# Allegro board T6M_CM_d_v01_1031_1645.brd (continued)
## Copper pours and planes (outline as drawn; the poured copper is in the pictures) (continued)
PV_VDDR_NODE1_V1 on TOP (solid shape): 46.98,11.32 47.03,11.31 47.07,11.28 47.6,10.76 48.55,10.76 48.86,10.76 48.95,10.72 48.98,10.63 48.98,10.24 48.97,10.22 48.98,10.21 48.98,9.97 48.95,9.88 48.86,9.84 47.62,9.84 47.35,9.58 46.78,9.58 46.66,9.7 46.66,11.29 46.69,11.32
PV_VDDR_NODE1_VREF on TOP (solid shape): 49.07,8.41 49.07,7.82 48.66,7.41 47.65,7.41 47.32,7.08 46.64,7.08 46.42,7.29 46.42,8.43 46.48,8.49 49,8.49
PV_VDDR_NODE1_VREF_R on TOP (solid shape): 25.34,11.39 25.34,6.41 25.03,6.11 23.95,6.11 23.69,6.36 23.69,9.65 22.81,10.54 22.21,10.54 22.16,10.59 22.16,11.29 22.34,11.47 25.26,11.47
PV_VTT_DDR_NODE1 on TOP (solid shape): outline of 267 points within 115.18,16.72 127.52,30.28
PV_VTT_DDR_NODE1 on BOTTOM (solid shape): 127.21,27.16 127.3,27.12 127.34,27.03 127.34,26.28 127.43,26.19 127.43,25.93 127.84,25.53 127.84,24.77 127.71,24.65 127.09,24.65 126.95,24.8 126.93,24.9 126.93,24.97 126.59,25.31 125.82,26.08 125.82,27.03 125.86,27.12 125.95,27.16
PV_VTT_DDR_NODE1_REFIN on TOP (solid shape): 130.01,26.2 130.01,25.68 130.22,25.47 130.22,23.66 129.97,23.41 128.36,23.41 128.31,23.46 128.31,24.74 128.38,24.81 128.91,24.81 128.99,24.89 128.99,25.28 129.04,25.34 129.04,26.35 129.06,26.37 129.85,26.37
PV_VTT_DDR_NODE1_REFOUT on TOP (solid shape): 126.55,21.17 126.55,20.06 125.95,19.46 125.95,18.99 125.76,18.8 125.02,18.8 124.95,18.87 124.95,21.03 125.12,21.2 126.53,21.2
PWRGD_NODE1_P1V05_SUS_PG on TOP (solid shape): 106.49,136.85 106.49,135.8 106.47,135.78 103.66,135.78 103.22,136.22 103.22,137.39 103.27,137.44 105.9,137.44
SATA_P7 on TOP (solid shape): 165.56,55.07 165.74,55 165.81,54.81 165.91,54.33 166.21,53.94 166.25,53.89 166.26,53.84 166.26,51.33 166.11,51.18 163.39,51.18 162.82,51.75 157.87,51.75 157.83,51.75 157.79,51.78 157.73,51.84 156.71,51.84 156.54,51.84 156.42,51.96 156.39,52 156.38,52.05 156.38,54.87 156.59,55.07
SATA_P7 on BOTTOM (solid shape): 165.56,55.07 165.74,55 165.81,54.81 165.91,54.33 166.21,53.94 166.25,53.89 166.26,53.84 166.26,51.33 166.11,51.18 163.39,51.18 162.82,51.75 157.87,51.75 157.83,51.75 157.79,51.78 157.73,51.84 156.71,51.84 156.54,51.84 156.42,51.96 156.39,52 156.38,52.05 156.38,54.87 156.59,55.07
SATA_VCONT_NODE1 on TOP (solid shape): 149.33,69.39 149.33,66.78 149.13,66.58 147.73,66.58 147.59,66.72 147.59,69.2 147.88,69.49 149.23,69.49
SATA_VCONT_NODE1 on TOP (solid shape): 162.41,70.06 162.41,69.78 162.19,69.56 162.19,69.34 162.04,69.19 162.04,67.92 161.99,67.88 161.08,67.88 161.04,67.93 161.04,68.08 161.05,68.14 161.36,68.44 161.46,68.8 161.46,69.57 161.46,69.64 161.49,69.7 161.98,70.19 162.28,70.19
SIO_AVCC on TOP (solid shape): 153.93,28.73 154.43,28.23 156.59,28.23 156.85,27.97 156.85,26.96 156.66,26.77 156.53,26.77 156.16,26.4 156.16,26.01 156.12,25.97 155.36,25.97 155.06,26.27 153.97,26.27 153.66,25.96 153.05,25.96 152.95,26.06 152.95,28.39 153.67,29.11 153.67,30.97 153.93,30.97
SIO_VCCH on TOP (solid shape): 138.55,34.42 138.55,33.5 138.28,33.23 137.65,33.23 137.36,32.95 137.36,31.67 137.32,31.58 137.24,31.54 136.43,31.54 135.89,31.01 135.8,30.97 135.71,31.01 135.22,31.5 135.22,31.86 135.48,32.12 135.51,32.12 135.51,32.16 135.58,32.23 135.58,34.58 135.6,34.61 138.37,34.61
SIO_VCCH on BOTTOM (solid shape): 138.19,34.49 138.19,33.72 137.99,33.51 137.52,33.51 137.36,33.36 137.36,31.11 137.03,30.78 135.94,30.78 135.02,31.7 135.02,34.43 135.19,34.61 138.08,34.61
SW_P1V05_NODE1_BT on TOP (solid shape): 31.63,129.42 31.63,128.66 31.56,128.59 30.93,128.59 30.13,129.38 29.21,129.38 29.2,129.4 29.2,129.65 29.2,129.65 31.4,129.65
SW_P1V05_NODE1_DRVH on TOP (solid shape): 28.47,129.15 28.47,128.14 28.59,128.02 28.59,127.23 28.59,126.89 28.56,126.86 28.56,126.18 28.55,126.17 28.02,126.17 28,126.19 28,126.57 28.21,126.79 28.21,129.14 28.25,129.17 28.45,129.17
SW_P1V05_NODE1_DRVL on TOP (solid shape): 34.21,126.84 34.21,126.29 34.07,126.15 32.32,126.15 32.26,126.2 32.26,126.98 34.07,126.98
SW_P1V05_NODE1_DRVL on TOP (solid shape): 27.97,129.15 27.97,127.71 27.93,127.67 27.93,126.9 27.84,126.81 27.58,126.81 27.49,126.9 27.49,127.78 27.72,128.01 27.72,129.14 27.75,129.17 27.96,129.17
SW_P1V05_NODE1_DRVL on BOTTOM (solid shape): 31.36,127.08 32.84,127.08 32.87,127.05 33.09,126.98 33.31,127.05 33.35,127.08 34.2,127.08 34.28,127 34.28,126.34 34.24,126.25 34.15,126.21 30.77,126.21 29.01,127.97 27.99,127.97 27.94,127.92 27.94,126.89 27.79,126.74 27.25,126.74 27.17,126.81 26.91,127.06 26.91,128.68 26.95,128.77 27.04,128.81 29.63,128.81
SW_P1V05_NODE1_PH on TOP (solid shape): 30.73,128.22 31.61,128.22 31.97,127.87 31.97,123.65 32.18,123.45 33.37,123.45 33.48,123.34 33.48,120.59 33.36,120.47 30.13,120.47 29.97,120.63 29.97,126.9 29.85,127.02 29,127.02 28.94,127.08 28.94,128.12 28.71,128.35 28.71,129.07 28.75,129.11 29.84,129.11
SW_P1V05_NODE1_VIN_FLT on TOP (solid shape): 29.62,126.62 29.62,123.94 29.58,123.89 28.8,123.89 28.23,123.33 28.23,119.29 27.95,119.01 25.47,119.01 25.28,119.2 25.28,125.75 25.43,125.9 28.78,125.9 28.82,125.94 28.82,126.6 28.86,126.63 29.61,126.63
SW_P1V05_NODE1_VIN_FLT on BOTTOM (solid shape): 28.23,125.7 28.23,121.15 28.03,120.95 25.54,120.95 25.28,121.21 25.28,125.75 25.45,125.92 28.01,125.92
SW_P1V8_STB_NODE1_BT on TOP (solid shape): 113.24,154.11 113.24,153.19 112.81,152.76 110.99,152.76 110.92,152.84 110.92,153.89 111.17,154.14 113.21,154.14
SW_P1V8_STB_NODE1_PH on TOP (solid shape): 112.67,157.86 112.67,156.2 113.27,155.6 113.27,154.43 113.24,154.4 110.73,154.4 110.62,154.29 110.62,153.62 110.48,153.48 108.05,153.48 107.63,153.9 107.63,157.76 107.8,157.93 112.6,157.93
SW_P3V3_NODE1_BT on TOP (solid shape): 85.58,8.39 85.58,7.33 85.33,7.08 83.29,7.08 83.27,7.11 83.27,8.03 83.69,8.46 85.51,8.46
SW_P3V3_NODE1_PH on TOP (solid shape): 88.32,6.69 88.32,3.32 88.29,3.29 83.9,3.29 83.83,3.36 83.83,5.03 83.24,5.62 83.24,6.08 83.24,6.08 83.24,6.57 83.25,6.58 83.24,6.59 83.24,6.79 83.27,6.82 88.19,6.82
SW_P3V3_STB_NODE1_BT on TOP (solid shape): 61.34,111.92 61.34,110.86 61.1,110.61 59.05,110.61 59.03,110.64 59.03,111.57 59.46,111.99 61.27,111.99
SW_P3V3_STB_NODE1_PH on TOP (solid shape): 64.08,110.22 64.08,106.85 64.05,106.82 60.71,106.82 60.48,107.05 59.75,107.05 59.59,107.2 59.59,108.56 59,109.15 59,110.32 59.03,110.35 63.95,110.35
SW_P5V_STB_NODE1_BT on TOP (solid shape): 89.72,154.08 89.72,153.15 89.29,152.73 87.48,152.73 87.4,152.8 87.4,153.86 87.65,154.1 89.69,154.1
SW_P5V_STB_NODE1_PH on TOP (solid shape): 89.16,157.68 89.16,156.16 89.75,155.57 89.75,154.4 89.72,154.37 84.79,154.37 84.66,154.5 84.66,157.68 84.78,157.8 89.04,157.8
SW_PV_VDDR_NODE1_BT on TOP (solid shape): 52.14,9.56 52.52,9.56 53.14,8.94 53.97,8.94 54,8.91 54,8.09 53.84,7.93 53,7.93 51.51,9.42 51.24,9.42 51.23,9.44 51.23,9.54 51.25,9.57 52.14,9.57
SW_PV_VDDR_NODE1_DRVH on TOP (solid shape): 55.21,6.74 55.06,6.58 53.84,6.58 53.78,6.64 53.78,7.31 53.91,7.44 54.42,7.44 54.76,7.78 55.21,7.78
SW_PV_VDDR_NODE1_DRVH on TOP (solid shape): 53.54,11.04 53.54,10.79 52.99,10.24 52.16,10.24 52.15,10.23 51.25,10.23 51.24,10.24 51.24,10.36 51.25,10.37 52.51,10.37 53.28,11.14 53.44,11.14
SW_PV_VDDR_NODE1_DRVH on BOTTOM (solid shape): 55.19,9.72 55.19,6.69 55.02,6.52 53.85,6.52 53.79,6.58 53.79,9.14 52.63,10.29 52.63,10.57 53.23,11.17 53.75,11.17
SW_PV_VDDR_NODE1_DRVL on TOP (solid shape): 55.22,12 55.22,11.55 55.18,11.5 53.27,11.5 52.4,10.64 51.25,10.64 51.24,10.65 51.24,10.76 51.26,10.78 52.09,10.78 53.33,12.02 55.21,12.02
SW_PV_VDDR_NODE1_PH on TOP (solid shape): 60.63,12.42 60.63,9.33 60.55,9.24 53.28,9.24 52.71,9.81 52.6,9.81 52.59,9.82 51.25,9.82 51.23,9.84 51.23,9.96 51.25,9.98 53.12,9.98 53.2,9.98 54.46,11.24 57.7,11.24 57.93,11.47 57.93,12.62 57.99,12.68 60.38,12.68
SW_PV_VDDR_NODE1_VIN_FLT on TOP (solid shape): 57.5,8.83 57.5,8.05 58.07,7.48 63.67,7.48 63.95,7.2 63.95,5.26 63.75,5.05 61.19,5.05 60.53,4.4 53.11,4.4 52.97,4.54 52.97,5.63 53.06,5.73 55.11,5.73 55.47,6.08 55.47,7.99 55.4,8.06 54.78,8.06 54.76,8.08 54.76,8.86 54.77,8.88 57.45,8.88
SW_PV_VDDR_NODE1_VIN_FLT on BOTTOM (solid shape): 64.17,7.11 64.17,4.76 63.89,4.48 55.55,4.48 55.31,4.72 55.31,5.77 55.32,5.78 55.32,5.97 55.81,6.46 55.81,7.01 56.22,7.43 63.85,7.43
SW_VR_PVCCP_NODE1_VIN_FLT on TOP (solid shape): 131.09,127.44 131.09,124.35 130.93,124.18 130.2,124.18 127.65,124.18 126.98,124.18 126.91,124.11 123.41,124.11 123.22,123.92 123.22,123.22 123.18,123.13 123.09,123.09 122.53,123.09 122.46,123.16 122.46,127.22 122.62,127.37 123.18,127.37 123.27,127.46 131.07,127.46
SW_VR_PVCCP_NODE1_VIN_FLT on BOTTOM (solid shape): 131.11,127.31 131.11,124.29 131,124.18 130.2,124.18 127.65,124.18 126.88,124.18 126.8,124.11 123.41,124.11 123.22,123.92 123.22,123.22 123.18,123.13 123.09,123.09 122.53,123.09 122.46,123.16 122.46,127.22 122.62,127.37 123.18,127.37 123.27,127.46 130.96,127.46
USB_OC_PU on TOP (solid shape): 179.2,96.17 179.2,95.91 179.19,95.89 179.17,95.78 179.19,95.67 179.2,95.65 179.2,94.86 178.34,94 177.87,94 177.78,94.09 177.78,94.38 176.79,95.38 176.79,96.18 176.87,96.27 179.1,96.27
USBPWR_P0 on TOP (solid shape): outline of 212 points within 188.89,30.13 204.14,40.13
USBPWR_P0 on BOTTOM (solid shape): outline of 348 points within 183.86,30.1 206.49,40.52
USBPWR_P0 on IN1 (solid shape): outline of 397 points within 183.86,30.1 206.49,40.52
USBPWR_P0 on IN3 (solid shape): outline of 403 points within 185.9,30.1 204.36,40.52
USBPWR_P1 on TOP (solid shape): 196.95,59.87 196.95,58.61 196.56,58.22 193.55,58.22 192.77,58.39 191.99,58.22 190.53,58.22 188.81,56.5 188.81,53.28 189.67,52.41 189.67,50.47 189.57,50.37 189.53,50.34 189.48,50.33 184.24,50.33 183.63,50.94 183.63,55.34 184.14,55.86 185.31,55.86 189.68,60.22 196.6,60.22
USBPWR_P1 on BOTTOM (solid shape): outline of 307 points within 183.78,50.32 196.78,61.13
USBPWR_P1 on IN1 (solid shape): outline of 307 points within 183.78,50.32 196.78,61.13
USBPWR_P1 on IN3 (solid shape): outline of 307 points within 183.78,50.32 196.78,61.13
VR_PVCCP_NODE1_BOOT1 on TOP (solid shape): 123.06,132.62 123.06,130.49 123.08,130.47 123.08,128.75 122.91,128.58 121.37,128.58 121.33,128.62 121.33,129.1 121.51,129.29 121.84,129.29 122.17,129.62 122.17,132.48 121.65,133.01 121.65,133.14 121.66,133.15 122.54,133.15
VR_PVCCP_NODE1_EN on TOP (solid shape): 116.81,131.68 118.05,131.68 118.17,131.55 118.17,131.21 118.09,131.13 116.99,131.13 116.93,131.07 116.93,130.4 116.86,130.33 114.39,130.33 114.35,130.38 114.35,131.39 114.63,131.68 116.81,131.68
VR_PVCCP_NODE1_LGATE1 on TOP (solid shape): 118.63,123.64 118.63,122.92 118.62,122.91 117.35,122.91 117.22,123.04 116.17,123.04 116.13,123.06 116.1,123.08 116.05,123.13 116.03,123.19 116.03,123.64 116.05,123.66 118.6,123.66
VR_PVCCP_NODE1_LGATE1 on BOTTOM (solid shape): 121.01,132 121.01,130.52 120.75,130.26 119.85,130.26 119.68,130.43 119.68,130.88 120.07,131.27 120.07,131.98 120.21,132.12 120.89,132.12
VR_PVCCP_NODE1_LGATE1 on IN3 (solid shape): 120.71,131.36 120.71,128.5 118.93,126.72 118.93,123.25 118.65,122.98 116.95,122.98 116.92,122.99 116.75,123.03 116.57,122.99 116.54,122.98 116.2,122.98 116.14,123.03 116.1,123.05 116.05,123.09 116.03,123.16 116.03,123.65 116.18,123.8 117.68,123.8 117.87,123.99 117.87,127.32 119.64,129.09 119.64,131.23 119.99,131.57 120.51,131.57
VR_PVCCP_NODE1_PHASE1 on TOP (solid shape): 121.05,131.2 121.05,130.39 121.04,130.39 121.04,129.62 121.05,129.62 121.05,127.95 121.05,127.94 121.05,127.32 121.08,127.29 121.9,127.29 121.92,127.27 121.92,122.98 122.48,122.41 122.49,122.41 123.57,121.33 123.57,120.46 123.32,120.21 121.65,120.21 121.58,120.27 121.58,120.85 121.5,120.93 120.36,120.93 120.34,120.91 120.34,120.18 120.29,120.13 119.29,120.13 119.03,120.39 119.03,127.26 119.07,127.31 119.64,127.31 119.91,127.57 119.91,129.77 120.61,130.47 120.62,130.47 120.62,131.14 120.75,131.26 120.99,131.26
VR_PVCCP_NODE1_PVCC on TOP (solid shape): 119.66,131.6 119.66,131.11 119.54,130.99 119.54,129.95 119.45,129.85 117.42,129.85 117.37,129.9 117.37,130.75 117.48,130.86 118.24,130.86 119.04,131.65 119.61,131.65
VR_PVCCP_NODE1_UGATE1 on TOP (solid shape): 126.01,123.51 126.01,123.04 125.88,122.91 123.69,122.91 123.68,122.92 123.68,123.51 123.76,123.6 125.93,123.6
VR_PVCCP_NODE1_UGATE1 on TOP (solid shape): 121.82,132.44 121.82,130.63 121.81,130.62 121.81,129.78 121.77,129.69 121.68,129.65 121.43,129.65 121.34,129.69 121.3,129.78 121.3,129.88 121.29,129.88 121.29,130.13 121.31,130.13 121.31,131.31 121.25,131.37 121.25,131.56 121.26,131.57 121.26,132.64 121.34,132.72 121.54,132.72
VR_PVCCP_NODE1_UGATE1 on IN3 (solid shape): 121.91,131.53 121.96,131.52 122,131.49 122.42,131.07 122.42,125.65 124.17,123.9 125.7,123.9 126.02,123.59 126.02,122.98 125.87,122.83 122.91,122.83 121.22,124.52 121.22,131.48 121.27,131.53
VR_PVCCP_NODE1_VCC on TOP (solid shape): 123.7,139.85 123.7,138.9 123.41,138.61 123.01,138.61 122.88,138.48 122.87,138.47 122.85,138.45 122.85,137.35 122.96,137.24 122.96,137.04 122.85,136.92 122.63,136.92 122.23,137.32 122.22,137.32 122.11,137.43 122.11,138.07 122.12,138.09 122.12,138.74 122.74,139.36 122.74,139.43 122.82,139.5 122.82,139.74 122.85,139.83 122.94,139.87 123.68,139.87
VR_PVCCP_NODE1_VCC on BOTTOM (solid shape): 122.94,137.96 122.94,136.81 122.82,136.69 122.29,136.69 121.88,137.09 120.91,137.09 120.91,137.89 121.19,138.17 122.73,138.17
VSENSE_HSC_NODE1 on TOP (solid shape): 54.53,183.86 54.53,181.69 54.14,181.3 52.59,181.3 52.32,181.03 52.32,176.46 52.15,176.29 47.8,176.29 47.63,176.46 47.63,176.84 47.64,176.86 47.65,176.96 47.64,177.07 47.63,177.08 47.63,181.05 47.62,181.05 47.62,182.93 48.56,183.86 52.01,183.86 52.18,184.03 54.35,184.03
VSENSE_HSC_NODE1 on IN3 (solid shape): 52.86,182.11 52.86,179.17 52.07,178.39 46.19,178.39 45.97,178.51 45.96,178.76 46.03,178.87 46.05,179 45.86,179.34 45.47,179.33 45.22,179.33 45.09,179.55 45.09,182.12 45.14,182.17 52.8,182.17
N21550241 on TOP (solid shape): 125.94,47.32 125.94,45.96 126.2,45.71 126.2,44.35 126.11,44.26 125.01,44.26 124.54,44.73 124.54,47.22 124.72,47.39 125.87,47.39
N21581564 on TOP (solid shape): 27.33,75.1 27.33,69.14 27.28,69.09 25.48,69.09 24.51,70.06 24.51,75.24 24.75,75.47 26.95,75.47
N46114787 on TOP (solid shape): 130.14,47.84 130.14,44.49 129.94,44.3 128.87,44.3 128.84,44.33 128.84,47.88 128.94,47.98 130,47.98
N54065132 on BOTTOM (solid shape): outline of 435 points within 22.85,155.64 27.24,166.74

Small or netless copper shapes (teardrops, artwork), in the pictures only: 214 on TOP, 12 on BOTTOM, 15 on IN1, 17 on IN2, 5 on IN3

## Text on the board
Ref Des/Silkscreen Bottom: A | D | C | B | Rev:D | P/N:DAT6MTH3AD0
User.Comments: TEL:(03)327-2345 FAX:(03)397-3614 | PROJECT: | P/N: | DATE: | REV: | NO.188,WEN HWA 2ND RD. | KUEI SHAN HSIANG,TAO YUAN | SHIEN,TAIWAN R.O.C. | (.08inch) | R2mm | Layer | Irene | DAT6MTH3AD0 | 2012/10/31 | T6M_CM_D | D | 16 | Quanta
Ref Des/Silkscreen Top: CONSOLE | REDIRECTION | WDT_EN | VGA CONN | ATTENTION LED | H8 | LAN1 | B | CPU | A | E | 0 | 1 | BIOS SOCKET | 2 | 3 | 4 | CPLD2 | 5 | 6 | D | 7 | XDP CONN | DIMM SLOT | SW | C | SATA DOM PWR | CPLD1 JTAG | CPLD2 JTAG | CPLD3 | CPLD3 JTAG | TACKOVER_ENABLE | USB0 & USB1 | USB2 & USB3 | LAN2 | F | CPLD1 | DEBUG PWR CONN | TPM CONN | BATTERY SOCKET | COM4 | RST_BTN | COM3 | SATA CONN | PWR_BTN | STATUS LED
DISPLAY_BOTTOM: 164.1 | 177 | 190 | 17.1 | 0 | 87.1 | 10 | 3B | 3E | 3I | n | 164.05 | 17.05 | 1.6 | (4X) | 5 | R | 24 | 41.35 | 145.55 | 147.45 | 158.65 | 176 | 200 | TOP VIEW | NOT OFFICIAL DRAWING
User.5: 190 | 0 | 0.1 | 3.6 | ` | n | (4X) | 3 | 4 | 3.8 | 0.2 | 7 | 3B | 3E | 3I | 6 | R | (5X) | 17 | 200 | BOTTOM VIEW
User.6: 17.1 | 164.1 | 190 | 177 | 0.1 | 3.6 | ` | n | (4X) | 0.2 | 7 | 0 | 10 | 3B | 3E | 3I | 3.8 | 87.1 | 17.05 | 164.05 | 5 | R | 24 | 41.35 | 145.55 | 147.45 | 158.65 | 176 | 200
User.7: NOTE: (UNLESS OTHERWISE SPECIFIED): | ==================================== | 1.MATERIAL: 1.6+/-0.1 MM THICK , NEMA GRADE FR-4 , | 2.COMPONENTS DIMENSIONED TO PIN 1. | 3.INDICATED AREA SHALL BE: | A- COPPER FREE | B- COMPONENT FREE | C- CONDUCTOR FREE | D- THROUGH HOLE COMPONENT FREE. | E- COPPER PAD COVERED WITH SOLID SOLDER | MASK CONNECTED TO GROUND , (GROUND PAD)(W/VIA) | F- COPPER PAD COVERED WITH SOLID SOLDER | MASK CONNECTED TO GROUND , (GROUND PAD) | G- COMPONENT FREE, EXCEPT FOR INDICATED CONN. | H- VIA FREE. | I- TRACE FREE | 4. DRAWING FOR ECAD DESINGER REFERENCE ONLY . | ECAD LAYOUT SHALL MATCH LATEST PRO-E IDF | FILE | 17.1 | 164.1 | 0 | 190 | 177 | 0.1 | 3.6 | ` | n | (4X) | 0.2 | 7 | 3B | 3E | 3I | 8 | 5.41 | 7.07 | 10 | 3.8 | 87.1 | 17.05 | 164.05 | 5 | R | 24 | 41.35 | 112.2 | 145.55 | 147.45 | 158.65 | 176 | 200 | TOP VIEW
User.8: 208.7 | 182.8 | 195.7 | 26.8 | 0.1 | 3.6 | ` | n | 0 | 8.77 | (4X) | 0.2 | 7 | 5.41 | 95.8 | 26.75 | 10 | 3B | 3E | 3I | 3.8 | 182.75 | 5 | R | 24 | 41.35 | 112.2 | 145.55 | 147.45 | 158.65 | 176 | 200 | TOP VIEW
User.9: 1 | 2 | 3 | 6 | 9 | 7 | 8 | 4 | 5 | A | B | C | D | NOTE: (UNLESS OTHERWISE SPECIFIED): | ==================================== | 1.MATERIAL: 1.6+/-0.1 MM THICK , NEMA GRADE FR-4 , | 2.COMPONENTS DIMENSIONED TO PIN 1. | 3.INDICATED AREA SHALL BE: | A- COPPER FREE | B- COMPONENT FREE | C- CONDUCTOR FREE | D- THROUGH HOLE COMPONENT FREE. | E- COPPER PAD COVERED WITH SOLID SOLDER | MASK CONNECTED TO GROUND , (GROUND PAD)(W/VIA) | F- COPPER PAD COVERED WITH SOLID SOLDER | MASK CONNECTED TO GROUND , (GROUND PAD) | G- COMPONENT FREE, EXCEPT FOR INDICATED CONN. | H- VIA FREE. | I- TRACE FREE | 4. DRAWING FOR ECAD DESINGER REFERENCE ONLY . | ECAD LAYOUT SHALL MATCH LATEST PRO-E IDF | FILE | E | F | G | H | I | J | K | L | M | 208.7 | 182.8 | 170.7 | 70.8 | 88.8 | 30.8 | 62.8 | 26.8 | 0.1 | 3.6 | ` | n | 0 | 8.77 | (4X) | 0.2 | 95.8 | 5.41 | 3B | 3E | 3I | 26.75 | 10 | 3.8 | 182.75 | 74.15 | 32.15 | 1.6 | 100- | 10-50 | 50-100 | 0-10 | 0.10 | 0.20 | 0.25 | 0.15 | (10X) | 12 | R | 13.36 | 25 | 26 | 84.56 | 86.46 | 90 | 97.66 | 102.36 | 112.2 | 173.56 | 175 | 175.46 | 186.66 | 196.7 | 200 | (5X) | 17 | RANGE | TOLERENCE | TOP VIEW | BOTTOM VIEW
User.10: 1 | 2 | 3 | 6 | 9 | 7 | 8 | 4 | 5 | A | B | C | D | NOTE: (UNLESS OTHERWISE SPECIFIED): | ==================================== | 1.MATERIAL: 1.6+/-0.1 MM THICK , NEMA GRADE FR-4 , | 2.COMPONENTS DIMENSIONED TO PIN 1. | 3.INDICATED AREA SHALL BE: | A- COPPER FREE | B- COMPONENT FREE | C- CONDUCTOR FREE | D- THROUGH HOLE COMPONENT FREE. | E- COPPER PAD COVERED WITH SOLID SOLDER | MASK CONNECTED TO GROUND , (GROUND PAD)(W/VIA) | F- COPPER PAD COVERED WITH SOLID SOLDER | MASK CONNECTED TO GROUND , (GROUND PAD) | G- COMPONENT FREE, EXCEPT FOR INDICATED CONN. | H- VIA FREE. | I- TRACE FREE | 4. DRAWING FOR ECAD DESINGER REFERENCE ONLY . | ECAD LAYOUT SHALL MATCH LATEST PRO-E IDF | FILE | E | F | G | H | I | J | K | L | M | 208.7 | 182.8 | 170.7 | 70.8 | 88.8 | 30.8 | 62.8 | 26.8 | 0.1 | 3.6 | ` | n | 0 | (4X) | 0.2 | 95.8 | 5.41 | 3B | 3E | 3I | 26.75 | 10 | 8.77 | 3.8 | 182.75 | 74.15 | 32.15 | 1.6 | 100- | 10-50 | 50-100 | 0-10 | 0.10 | 0.20 | 0.25 | 0.15 | (10X) | 12 | R | 13.36 | 25 | 26 | 84.56 | 86.46 | 90 | 97.66 | 102.36 | 122.2 | 173.56 | 175 | 175.46 | 186.66 | 196.7 | 200 | (5X) | 17 | RANGE | TOLERENCE | TOP VIEW | BOTTOM VIEW
User.11: 208.7 | 182.8 | 170.7 | 70.8 | 88.8 | 30.8 | 62.8 | 26.8 | 0.1 | 3.6 | ` | n | 0 | (4X) | 0.2 | 7 | 95.8 | 5.41 | 3B | 3E | 3I | 8 | 188.25 | 26.75 | 10 | 8.77 | 3.8 | 182.75 | 74.15 | 32.15 | 1.6 | 5 | R | 12.36 | 25 | 26 | 83.56 | 85.46 | 90 | 96.66 | 103.36 | 122.2 | 174.56 | 175 | 176.46 | 187.66 | 196.7 | 200 | TOP VIEW
User.12: TOP | 1
User.13: BOTTOM | 10
User.14: SILK-TOP
User.15: SILK-BOT
User.16: MASK-TOP
User.17: MASK-BOT
User.18: FAB
User.19: PAST-TOP
User.20: PAST-BOT
User.21: GND1 | 2
User.22: VCC1 | 4
User.23: IN1 | 3
User.24: IN2 | 7
User.25: IN3 | 8
User.26: IN4 | 7
User.27: GND2 | 6
User.28: VCC2 | 5
User.29: PANEL
User.31: GND3 | 9
User.34: DETAIL A
User.37: FIGURE | SIZE | 10.0 | 22.0 | 26.0 | 33.0 | 36.0 | 40.0 | 41.0 | 44.0 | 46.0 | 48.0 | 56.0 | 57.0 | 90.0 | 213.0 | 42.0 | 47.0 | 50.0 | 59.0 | 65.0 | 118.0 | 120.0 | 142.0 | 150.0 | 158.0 | 124.0x28.0 | DRILL CHART: TOP to BOTTOM | ALL UNITS ARE IN MILS | TOLERANCE | +3.0/-3.0 | +4.0/-10.0 | +2.0/-2.0 | +4.0/-4.0 | PLATED | NON-PLATED | QTY | 8 | 10 | 4398 | 1612 | 12 | 7 | 15 | 25 | 2 | 1 | 30 | 4 | 16
